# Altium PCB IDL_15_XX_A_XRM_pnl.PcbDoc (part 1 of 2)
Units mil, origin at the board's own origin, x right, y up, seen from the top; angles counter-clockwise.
Board outline 6130 x 3614.17 mil, 6 copper layers (Top Layer - SIG1, Layer 2 - GND1, Layer 3 - SIG2, Layer 4 - SIG3, Layer 5 - GND2, Bottom Layer - SIG4), stack 49.592 mil thick; 576 components, 385 nets, 1280 pads, 0 vias.
Unrouted connection lines stored in the file: 895.
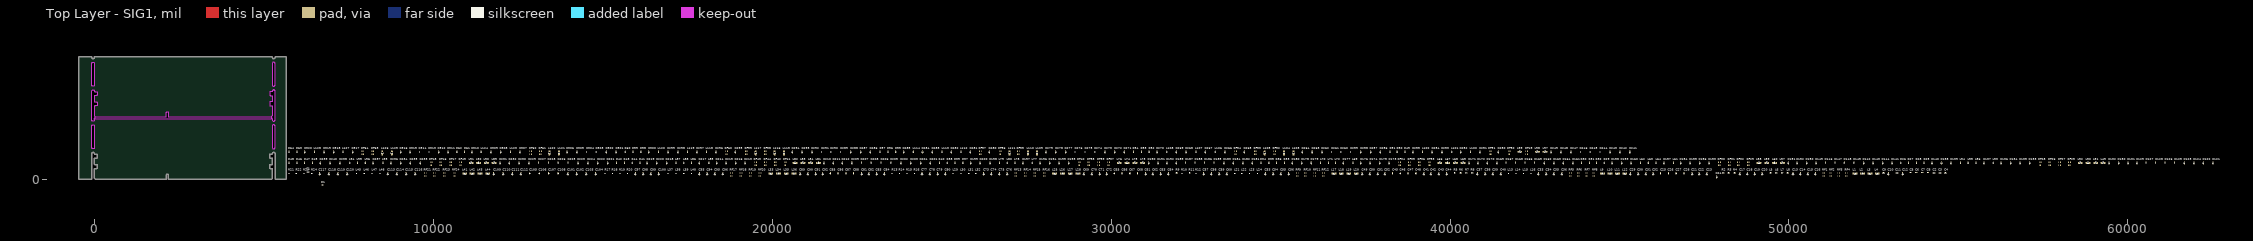
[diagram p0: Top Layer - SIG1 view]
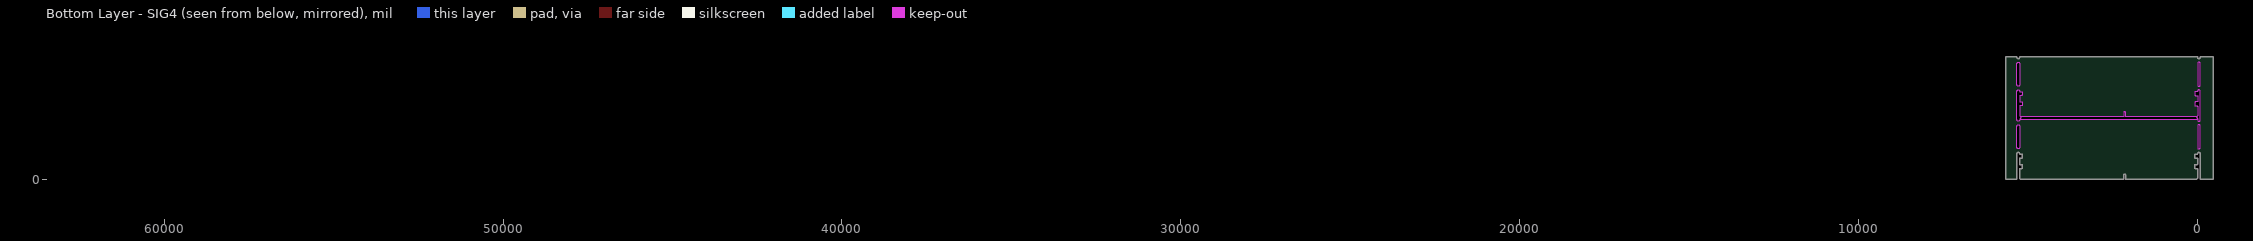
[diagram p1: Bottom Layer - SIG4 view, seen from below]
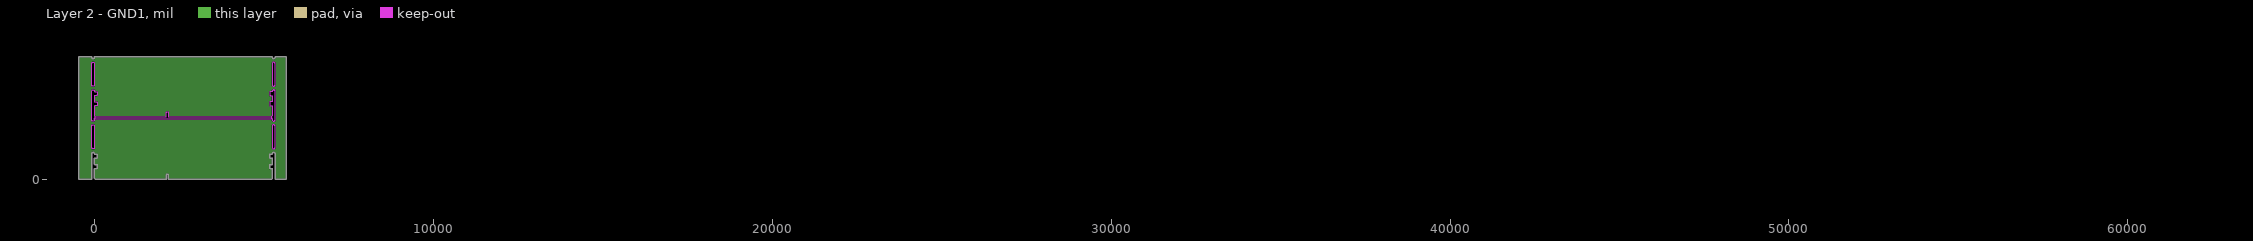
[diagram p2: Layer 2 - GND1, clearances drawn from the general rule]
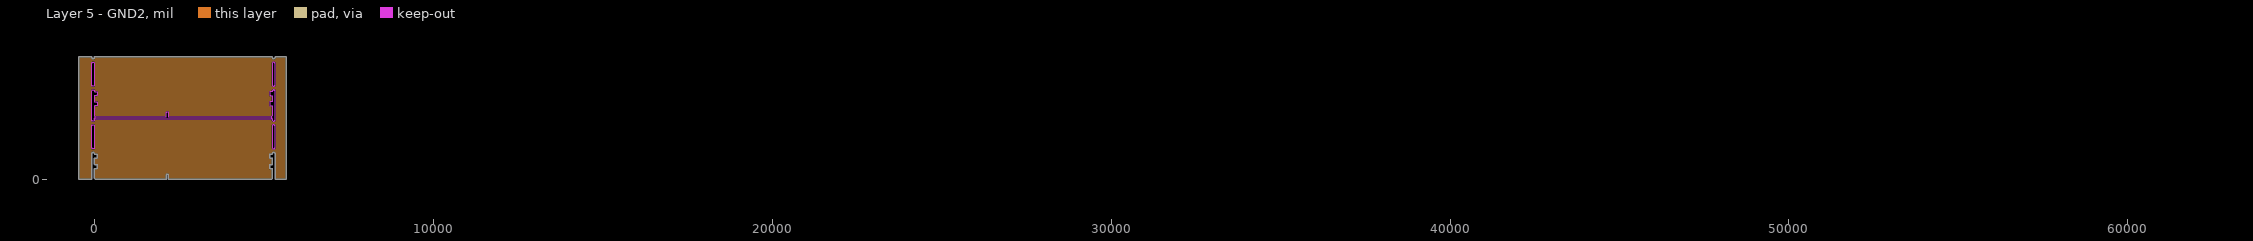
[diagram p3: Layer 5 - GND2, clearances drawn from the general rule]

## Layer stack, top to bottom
Top Solder: solder mask 0.4, Solder Resist, Dk 3.5
Top Layer - SIG1: signal copper 1.378
Dielectric 1: prepreg 8, FR-4, Dk 4.65
Layer 2 - GND1: plane copper 0.709
Dielectric 3: core 10, FR-4, Dk 4.65
Layer 3 - SIG2: signal copper 0.709
Dielectric 6: prepreg 8, FR-4, Dk 4.65
Layer 4 - SIG3: signal copper 0.709
Dielectric 5: core 10, FR-4, Dk 4.65
Layer 5 - GND2: plane copper 0.709
Dielectric 4: prepreg 8, FR-4, Dk 4.65
Bottom Layer - SIG4: signal copper 1.378
Bottom Solder: solder mask 0.4, Solder Resist, Dk 3.5

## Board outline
-465,0 -78.74,0 -78.74,751.97 cw(c-39.37,751.97) -39.37,791.34 cw(c-39.37,751.97) 0,751.97 ccw(c11.81,751.97) 11.81,740.16 62.99,740.16 cw(c62.99,720.47) 82.68,720.47 82.68,641.73 cw(c62.99,641.73) 62.99,622.05 11.81,622.05 ccw(c11.81,610.24) 0,610.24 0,444.88 ccw(c11.81,444.88) 11.81,433.07 62.99,433.07 cw(c62.99,413.39) 82.68,413.39 82.68,334.65 cw(c62.99,334.65) 62.99,314.96 11.81,314.96 ccw(c11.81,303.15) 0,303.15 0,29.53 29.53,0 2115.16,0 ccw(c2115.16,7.87) 2123.03,7.87 2123.03,120.08 cw(c2152.56,120.08) 2152.56,149.61 cw(c2152.56,120.08) 2182.09,120.08 2182.09,7.87 ccw(c2189.96,7.87) 2189.96,0 5220.47,0 5250,29.53 5250,303.15 ccw(c5238.19,303.15) 5238.19,314.96 5187.01,314.96 cw(c5187.01,334.65) 5167.32,334.65 5167.32,413.39 cw(c5187.01,413.39) 5187.01,433.07 5238.19,433.07 ccw(c5238.19,444.88) 5250,444.88 5250,610.24 ccw(c5238.19,610.24) 5238.19,622.05 5187.01,622.05 cw(c5187.01,641.73) 5167.32,641.73 5167.32,720.47 cw(c5187.01,720.47) 5187.01,740.16 5238.19,740.16 ccw(c5238.19,751.97) 5250,751.97 cw(c5289.37,751.97) 5289.37,791.34 cw(c5289.37,751.97) 5328.74,751.97 5328.74,0 5665,0 5665,3614 5328.74,3614 5328.74,3594.49 cw(c5289.37,3594.49) 5289.37,3555.12 cw(c5289.37,3594.49) 5250,3594.49 5250,3614.17 0,3614.17 0,3594.49 cw(c-39.37,3594.49) -39.37,3555.12 cw(c-39.37,3594.49) -78.74,3594.49 -78.74,3614 -465,3614
cut-out: -78.74,3413.39 cw(c-39.37,3413.39) -39.37,3452.76 cw(c-39.37,3413.39) 0,3413.39 0,2779.53 cw(c-39.37,2779.53) -39.37,2740.16 cw(c-39.37,2779.53) -78.74,2779.53
cut-out: -78.74,2598.43 cw(c-39.37,2598.43) -39.37,2637.8 cw(c-39.37,2598.43) 0,2598.43 ccw(c11.81,2598.43) 11.81,2586.61 62.99,2586.61 cw(c62.99,2566.93) 82.68,2566.93 82.68,2488.19 cw(c62.99,2488.19) 62.99,2468.5 11.81,2468.5 ccw(c11.81,2456.69) 0,2456.69 0,2291.34 ccw(c11.81,2291.34) 11.81,2279.53 62.99,2279.53 cw(c62.99,2259.84) 82.68,2259.84 82.68,2181.1 cw(c62.99,2181.1) 62.99,2161.42 11.81,2161.42 ccw(c11.81,2149.61) 0,2149.61 0,1875.98 29.53,1846.46 0,1767.72 0,1748.03 cw(c-39.37,1748.03) -39.37,1708.66 cw(c-39.37,1748.03) -78.74,1748.03
cut-out: 0,1767.72 29.53,1846.46 2115.16,1846.46 ccw(c2115.16,1854.33) 2123.03,1854.33 2123.03,1966.54 cw(c2152.56,1966.54) 2152.56,1996.06 cw(c2152.56,1966.54) 2182.09,1966.54 2182.09,1854.33 ccw(c2189.96,1854.33) 2189.96,1846.46 5220.47,1846.46 5250,1767.72
cut-out: 5328.74,2598.43 ccw(c5289.37,2598.43) 5289.37,2637.8 ccw(c5289.37,2598.43) 5250,2598.43 cw(c5238.19,2598.42) 5238.19,2586.61 5187.01,2586.61 ccw(c5187.01,2566.93) 5167.32,2566.93 5167.32,2488.19 ccw(c5187.01,2488.19) 5187.01,2468.5 5238.19,2468.5 cw(c5238.19,2456.69) 5250,2456.69 5250,2291.34 cw(c5238.19,2291.34) 5238.19,2279.53 5187.01,2279.53 ccw(c5187.01,2259.84) 5167.32,2259.84 5167.32,2181.1 ccw(c5187.01,2181.1) 5187.01,2161.42 5238.19,2161.42 cw(c5238.19,2149.61) 5250,2149.61 5250,1875.98 5220.47,1846.46 5212,1799 5250,1767.72 5250,1747.94 ccw(c5289.37,1748.03) 5328.74,1748.03
cut-out: 5328.74,1566.93 ccw(c5289.37,1566.93) 5289.37,1606.3 ccw(c5289.37,1566.93) 5250,1566.93 5250,933.07 ccw(c5289.37,933.07) 5289.37,893.7 ccw(c5289.37,933.07) 5328.74,933.07
cut-out: 5328.74,3413.39 ccw(c5289.37,3413.39) 5289.37,3452.76 ccw(c5289.37,3413.39) 5250,3413.39 5250,2779.53 ccw(c5289.37,2779.53) 5289.37,2740.16 ccw(c5289.37,2779.53) 5328.74,2779.53
cut-out: -78.74,1566.93 cw(c-39.37,1566.93) -39.37,1606.3 cw(c-39.37,1566.93) 0,1566.93 0,933.07 cw(c-39.37,933.07) -39.37,893.7 cw(c-39.37,933.07) -78.74,933.07

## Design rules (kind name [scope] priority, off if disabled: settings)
Clearance Clearance_KeepOut [Iskeepout] p1: gap=20
Clearance [All] p2: gap=7
HoleSize [All] p1: absolutevalues=TRUE maxlimit=129.92 minlimit=11.81 maxpercent=80.000 minpercent=20.000
MinimumSolderMaskSliver [All] p1: minsoldermaskwidth=5
PlaneClearance [All] p1: clearance=10
PlaneConnect PlaneConnect_vIA [ISvIA] p1: planeconnectstyle=Direct reliefexpansion=20 reliefentries=4 reliefconductorwidth=10 reliefairgap=10
PlaneConnect [All] p2: planeconnectstyle=Relief reliefexpansion=12 reliefentries=4 reliefconductorwidth=10 reliefairgap=8
PolygonConnect PolygonConnect_Via [IsVia or HasFootprint('ChipFET1206-8') or HasFootprint('MAXB2MPCBV') or HasFootprint('MAXB5MPCBV') or HasFootprint('MAXB6MPCBV')] p1: connectstyle=Direct reliefconductorwidth=10 reliefentries=4 polygonreliefangle="90 Angle" airgapwidth=10
PolygonConnect PolygonConnect_Main [All] p2: connectstyle=Relief reliefconductorwidth=10 reliefentries=4 polygonreliefangle="90 Angle" airgapwidth=10
RoomDefinition IDL_15_XX_A_XRM(6) [InComponentClass('IDL_15_XX_A_XRM(6)')] p1: confinementstyle=ConfineIn formatcopy=TRUE lockcomponents=FALSE outline 5709.39,685.64 45498.74,685.64 45498.74,963.21 5709.39,963.21
RoomDefinition IDL_15_XX_A_XRM(5) [InComponentClass('IDL_15_XX_A_XRM(5)')] p2: confinementstyle=ConfineIn formatcopy=TRUE lockcomponents=FALSE outline 5709.39,370.66 62693.47,370.66 62693.47,636.42 5709.39,636.42
RoomDefinition IDL_15_XX_A_XRM(4) [InComponentClass('IDL_15_XX_A_XRM(4)')] p3: confinementstyle=ConfineIn formatcopy=TRUE lockcomponents=FALSE outline 5709.39,55.68 5982.04,55.68 5982.04,225.97 5709.39,225.97
RoutingVias [All] p1: holewidth=11.81 width=25.59 viastyle="Through Hole" minholewidth=11.81 minwidth=25.59 maxholewidth=39.37 maxwidth=59.06
SilkToSilkClearance [All] p1: silktosilkclearance=5
SilkToSolderMaskClearance SilkscreenOverComponentPads [IsPad] p1: minsilkscreentomaskgap=5 clearancetoexposedcopper=TRUE
SolderMaskExpansion [All] p1: expansion=2
Width Width_Logo [HasFootprint('ITECH_LOGO')] p1: maxlimit=10 minlimit=1 preferedwidth=2
Width [All] p2: maxlimit=150 minlimit=6 preferedwidth=10 toplayer_prefwidth=8 midlayer1_prefwidth=8 midlayer2_minwidth=10 midlayer2_maxwidth=10 bottomlayer_prefwidth=8 minimp=50.000000 maximp=50.000000 favimp=50.000000
24 further rules are at their usual default settings.

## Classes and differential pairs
component class IDL_15_XX_A_XRM(3): K1
component class IDL_15_XX_A_XRM(4): C1 C2 C3 C4 C5 C6 C7 C8 C9 C10 C11 C12 C13 C14 C15 C16 C17 C18 C19 C20 C21 C22 C23 C24 C25 C26 C27 C28 C29 C30 C31 C32 C33 C34 C35 C36 C37 C38 C39 C40 C41 C42 C43 C44 C45 C46 C47 C48 C49 C50 C51 C52 C53 C54 C55 C56 C57 C58 C59 C60 C61 C62 C63 C64 C65 C66 C67 C68 C69 C70 C71 C72 C73 C74 C75 C76 C77 C78 C79 C80 C81 C82 C83 C84 C85 C86 C87 C88 C89 C90 C91 C92 C93 C94 C95 C96 C97 C98 C99 C100 C101 C102 C103 C104 C105 C106 C107 C108 C109 C110 C111 C112 C113 C114 C115 C116 C117 C118 C119 C120 L1 L2 L3 L4 L5 L6 L7 L8 L9 L10 L11 L12 L13 L14 L15 L16 L17 L18 L19 L20 L21 L22 L23 L24 L25 L26 L27 L28 L29 L30 L31 L32 L33 L34 L35 L36 L37 L38 L39 L40 L41 L42 L43 L44 L45 L46 L47 L48 R1 R2 R3 R4 R5 R6 R7 R8 R9 R10 R11 R12 R13 R14 R15 R16 R17 R18 R19 R20 R21 R22 R23 R24 RF1 RF2 RF3 RF4 RF5 RF6 RF7 RF8 RF9 RF10 RF11 RF12 RF13 RF14 RF15 RF16 RF17 RF18 RF19 RF20 RF21 RF22 RF23 RF24
component class IDL_15_XX_A_XRM(5): C121 C122 C123 C124 C125 C126 C127 C128 C129 C130 C131 C132 C133 C134 C135 C136 C137 C138 C139 C140 C141 C142 C143 C144 C145 C146 C147 C148 C149 C150 C151 C152 C153 C154 C155 C156 C157 C158 C159 C160 C161 C162 C163 C164 C165 C166 C167 C168 C169 C170 C171 C172 C173 C174 C175 C176 C177 C178 C179 C180 C181 C182 C183 C184 C185 C186 C187 C188 C189 C190 C191 C192 C193 C194 C195 C196 C197 C198 C199 C200 C201 C202 C203 C204 C205 C206 C207 C208 C209 C210 C211 C212 C213 C214 C215 C216 C217 C218 C219 C220 C221 C222 C223 C224 C225 C226 C227 C228 C229 C230 C231 C232 C233 C234 C235 C236 C237 C238 C239 C240 L49 L50 L51 L52 L53 L54 L55 L56 L57 L58 L59 L60 L61 L62 L63 L64 L65 L66 L67 L68 L69 L70 L71 L72 L73 L74 L75 L76 L77 L78 L79 L80 L81 L82 L83 L84 L85 L86 L87 L88 L89 L90 L91 L92 L93 L94 L95 L96 R25 R26 R27 R28 R29 R30 R31 R32 R33 R34 R35 R36 R37 R38 R39 R40 R41 R42 R43 R44 R45 R46 R47 R48 RF25 RF26 RF27 RF28 RF29 RF30 RF31 RF32 RF33 RF34 RF35 RF36 RF37 RF38 RF39 RF40 RF41 RF42 RF43 RF44 RF45 RF46 RF47 RF48
component class IDL_15_XX_A_XRM(6): C241 C242 C243 C244 C245 C246 C247 C248 C249 C250 C251 C252 C253 C254 C255 C256 C257 C258 C259 C260 C261 C262 C263 C264 C265 C266 C267 C268 C269 C270 C271 C272 C273 C274 C275 C276 C277 C278 C279 C280 C281 C282 C283 C284 C285 C286 C287 C288 C289 C290 C291 C292 C293 C294 C295 C296 C297 C298 C299 C300 C301 C302 C303 C304 C305 C306 C307 C308 C309 C310 C311 C312 C313 C314 C315 C316 C317 C318 C319 C320 L97 L98 L99 L100 L101 L102 L103 L104 L105 L106 L107 L108 L109 L110 L111 L112 L113 L114 L115 L116 L117 L118 L119 L120 L121 L122 L123 L124 L125 L126 L127 L128 R49 R50 R51 R52 R53 R54 R55 R56 R57 R58 R59 R60 R61 R62 R63 R64 RF49 RF50 RF51 RF52 RF53 RF54 RF55 RF56 RF57 RF58 RF59 RF60 RF61 RF62 RF63 RF64

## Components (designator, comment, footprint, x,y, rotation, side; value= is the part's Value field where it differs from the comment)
C1 "10nF" CC0603RF1R 6301.18,216.54 r0 top
C2 "10nF" CC0603RF1R 54284.6,185.61 r0 top
C3 "10nF" CC0603RF1R 54453.9,185.61 r0 top
C4 "10nF" CC0603RF1R 54624.18,185.61 r0 top
C5 "100nF" CC0402N1X 53589.68,192.5 r0 top
C6 "100nF" CC0402N1X 53759.97,192.5 r0 top
C7 "100nF" CC0402N1X 53930.25,192.5 r0 top
C8 "100nF" CC0402N1X 54100.53,192.5 r0 top
C9 "1uF" CC0603RF1R 52792.4,185.61 r0 top
C10 "1uF" CC0603RF1R 52937.09,160.02 r90 top
C11 "1uF" CC0603RF1R 53183.17,185.61 r0 top
C12 "1uF" CC0603RF1R 53356.4,160.02 r90 top
C13 "10nF" CC0603RF1R 50120.02,160.02 r90 top
C14 "10nF" CC0603RF1R 50340.51,160.02 r90 top
C15 "10nF" CC0603RF1R 50560.01,160.02 r90 top
C16 "10nF" CC0603RF1R 50780.49,160.02 r90 top
C17 "10nF" CC0603RF1R 48550.07,160.02 r90 top
C18 "10nF" CC0603RF1R 48770.55,160.02 r90 top
C19 "10nF" CC0603RF1R 48990.05,160.02 r90 top
C20 "10nF" CC0603RF1R 49210.53,160.02 r90 top
C21 "10nF" CC0603RF1R 47140.55,160.02 r90 top
C22 "10nF" CC0603RF1R 47350.2,160.02 r90 top
C23 "10nF" CC0603RF1R 47580.53,160.02 r90 top
C24 "10nF" CC0603RF1R 47867.13,66.93 r90 top
C25 "100nF" CC0402N1X 46213.34,173.8 r90 top
C26 "100nF" CC0402N1X 46443.66,173.8 r90 top
C27 "100nF" CC0402N1X 46673,173.8 r90 top
C28 "100nF" CC0402N1X 46903.33,173.8 r90 top
C29 "1uF" CC0603RF1R 45320.58,160.02 r90 top
C30 "1uF" CC0603RF1R 45550.9,160.02 r90 top
C31 "1uF" CC0603RF1R 45780.24,160.02 r90 top
C32 "1uF" CC0603RF1R 45990.89,160.02 r90 top
C33 "10nF" CC0603RF1R 42607.85,160.02 r90 top
C34 "10nF" CC0603RF1R 42837.19,160.02 r90 top
C35 "10nF" CC0603RF1R 43067.51,160.02 r90 top
C36 "10nF" CC0603RF1R 43297.84,160.02 r90 top
C37 "10nF" CC0603RF1R 40807.56,160.02 r90 top
C38 "10nF" CC0603RF1R 41037.89,160.02 r90 top
C39 "10nF" CC0603RF1R 41267.23,160.02 r90 top
C40 "10nF" CC0603RF1R 41497.56,160.02 r90 top
C41 "10nF" CC0603RF1R 39227.76,160.02 r90 top
C42 "10nF" CC0603RF1R 39437.42,160.02 r90 top
C43 "10nF" CC0603RF1R 39667.74,160.02 r90 top
C44 "10nF" CC0603RF1R 39898.07,160.02 r90 top
C45 "100nF" CC0402N1X 38300.55,173.8 r90 top
C46 "100nF" CC0402N1X 38530.88,173.8 r90 top
C47 "100nF" CC0402N1X 38761.2,173.8 r90 top
C48 "100nF" CC0402N1X 38990.54,173.8 r90 top
C49 "1uF" CC0603RF1R 37407.79,160.02 r90 top
C50 "1uF" CC0603RF1R 37638.12,160.02 r90 top
C51 "1uF" CC0603RF1R 37867.46,160.02 r90 top
C52 "1uF" CC0603RF1R 38078.1,160.02 r90 top
C53 "10nF" CC0603RF1R 34548.4,160.02 r90 top
C54 "10nF" CC0603RF1R 34778.72,160.02 r90 top
C55 "10nF" CC0603RF1R 35008.07,160.02 r90 top
C56 "10nF" CC0603RF1R 35238.39,160.02 r90 top
C57 "10nF" CC0603RF1R 32728.43,160.02 r90 top
C58 "10nF" CC0603RF1R 32958.75,160.02 r90 top
C59 "10nF" CC0603RF1R 33188.1,160.02 r90 top
C60 "10nF" CC0603RF1R 33418.42,160.02 r90 top
C61 "10nF" CC0603RF1R 31018.7,160.02 r90 top
C62 "10nF" CC0603RF1R 31228.35,160.02 r90 top
C63 "10nF" CC0603RF1R 31458.68,160.02 r90 top
C64 "10nF" CC0603RF1R 31689.01,160.02 r90 top
C65 "100nF" CC0402N1X 30091.49,173.8 r90 top
C66 "100nF" CC0402N1X 30321.81,173.8 r90 top
C67 "100nF" CC0402N1X 30551.16,173.8 r90 top
C68 "100nF" CC0402N1X 30781.48,173.8 r90 top
C69 "1uF" CC0603RF1R 29198.73,160.02 r90 top
C70 "1uF" CC0603RF1R 29429.05,160.02 r90 top
C71 "1uF" CC0603RF1R 29658.4,160.02 r90 top
C72 "1uF" CC0603RF1R 29869.04,160.02 r90 top
C73 "10nF" CC0603RF1R 26238.94,160.02 r90 top
C74 "10nF" CC0603RF1R 26469.26,160.02 r90 top
C75 "10nF" CC0603RF1R 26699.59,160.02 r90 top
C76 "10nF" CC0603RF1R 26928.93,160.02 r90 top
C77 "10nF" CC0603RF1R 24418.97,160.02 r90 top
C78 "10nF" CC0603RF1R 24649.29,160.02 r90 top
C79 "10nF" CC0603RF1R 24879.62,160.02 r90 top
C80 "10nF" CC0603RF1R 25108.96,160.02 r90 top
C81 "10nF" CC0603RF1R 22639.35,160.02 r90 top
C82 "10nF" CC0603RF1R 22849.99,160.02 r90 top
C83 "10nF" CC0603RF1R 23079.33,160.02 r90 top
C84 "10nF" CC0603RF1R 23309.66,160.02 r90 top
C85 "100nF" CC0402N1X 21713.13,173.8 r90 top
C86 "100nF" CC0402N1X 21942.47,173.8 r90 top
C87 "100nF" CC0402N1X 22172.79,173.8 r90 top
C88 "100nF" CC0402N1X 22402.14,173.8 r90 top
C89 "1uF" CC0603RF1R 20819.38,160.02 r90 top
C90 "1uF" CC0603RF1R 21049.71,160.02 r90 top
C91 "1uF" CC0603RF1R 21280.03,160.02 r90 top
C92 "1uF" CC0603RF1R 21489.69,160.02 r90 top
C93 "10nF" CC0603RF1R 17849.75,160.02 r90 top
C94 "10nF" CC0603RF1R 18080.07,160.02 r90 top
C95 "10nF" CC0603RF1R 18310.4,160.02 r90 top
C96 "10nF" CC0603RF1R 18539.74,160.02 r90 top
C97 "10nF" CC0603RF1R 15959.89,160.02 r90 top
C98 "10nF" CC0603RF1R 16190.22,160.02 r90 top
C99 "10nF" CC0603RF1R 16420.54,160.02 r90 top
C100 "10nF" CC0603RF1R 16649.89,160.02 r90 top
C101 "10nF" CC0603RF1R 13970.62,160.02 r90 top
C102 "10nF" CC0603RF1R 14230.48,160.02 r90 top
C103 "10nF" CC0603RF1R 14511,160.02 r90 top
C104 "10nF" CC0603RF1R 14790.54,160.02 r90 top
C105 "100nF" CC0402N1X 12843.6,173.8 r90 top
C106 "100nF" CC0402N1X 13124.12,173.8 r90 top
C107 "100nF" CC0402N1X 13403.67,173.8 r90 top
C108 "100nF" CC0402N1X 13683.21,173.8 r90 top
C109 "1uF" CC0603RF1R 11780.55,160.02 r90 top
C110 "1uF" CC0603RF1R 12061.08,160.02 r90 top
C111 "1uF" CC0603RF1R 12330.78,160.02 r90 top
C112 "1uF" CC0603RF1R 12580.79,160.02 r90 top
C113 "10nF" CC0603RF1R 8654.42,160.02 r90 top
C114 "10nF" CC0603RF1R 8925.1,160.02 r90 top
C115 "10nF" CC0603RF1R 9194.8,160.02 r90 top
C116 "10nF" CC0603RF1R 9464.5,160.02 r90 top
C117 "10nF" CC0603RF1R 6644.48,160.02 r90 top
C118 "10nF" CC0603RF1R 6915.16,160.02 r90 top
C119 "10nF" CC0603RF1R 7184.86,160.02 r90 top
C120 "10nF" CC0603RF1R 7454.56,160.02 r90 top
C121 "10nF" CC0603RF1R 62507.44,475 r90 top
C122 "10nF" CC0603RF1R 62227.9,475 r90 top
C123 "10nF" CC0603RF1R 61667.83,475 r90 top
C124 "10nF" CC0603RF1R 61947.37,475 r90 top
C125 "100nF" CC0402N1X 61380.42,488.78 r90 top
C126 "100nF" CC0402N1X 61100.87,488.78 r90 top
C127 "100nF" CC0402N1X 60540.81,488.78 r90 top
C128 "100nF" CC0402N1X 60820.35,488.78 r90 top
C129 "1uF" CC0603RF1R 60268.16,475 r90 top
C130 "1uF" CC0603RF1R 59727.78,475 r90 top
C131 "1uF" CC0603RF1R 60007.32,475 r90 top
C132 "1uF" CC0603RF1R 59448.23,475 r90 top
C133 "10nF" CC0603RF1R 57101.66,475 r90 top
C134 "10nF" CC0603RF1R 56541.6,475 r90 top
C135 "10nF" CC0603RF1R 56821.14,475 r90 top
C136 "10nF" CC0603RF1R 56261.07,475 r90 top
C137 "10nF" CC0603RF1R 55751.2,475 r90 top
C138 "10nF" CC0603RF1R 54502.13,475 r90 top
C139 "10nF" CC0603RF1R 54781.67,475 r90 top
C140 "10nF" CC0603RF1R 54221.6,475 r90 top
C141 "10nF" CC0603RF1R 53042.41,475 r90 top
C142 "10nF" CC0603RF1R 52201.82,475 r90 top
C143 "10nF" CC0603RF1R 52482.34,475 r90 top
C144 "10nF" CC0603RF1R 52761.88,475 r90 top
C145 "100nF" CC0402N1X 51915.39,488.78 r90 top
C146 "100nF" CC0402N1X 51074.79,488.78 r90 top
C147 "100nF" CC0402N1X 51355.32,488.78 r90 top
C148 "100nF" CC0402N1X 51634.86,488.78 r90 top
C149 "1uF" CC0603RF1R 50802.14,475 r90 top
C150 "1uF" CC0603RF1R 50522.6,475 r90 top
C151 "1uF" CC0603RF1R 49982.22,475 r90 top
C152 "1uF" CC0603RF1R 50242.08,475 r90 top
C153 "10nF" CC0603RF1R 47642.54,475 r90 top
C154 "10nF" CC0603RF1R 46802.93,475 r90 top
C155 "10nF" CC0603RF1R 47082.47,475 r90 top
C156 "10nF" CC0603RF1R 47363,475 r90 top
C157 "10nF" CC0603RF1R 46312.75,475 r90 top
C158 "10nF" CC0603RF1R 44783.15,475 r90 top
C159 "10nF" CC0603RF1R 45062.69,475 r90 top
C160 "10nF" CC0603RF1R 45343.22,475 r90 top
C161 "10nF" CC0603RF1R 43623.64,475 r90 top
C162 "10nF" CC0603RF1R 42783.05,475 r90 top
C163 "10nF" CC0603RF1R 43063.58,475 r90 top
C164 "10nF" CC0603RF1R 43343.12,475 r90 top
C165 "100nF" CC0402N1X 42496.62,488.78 r90 top
C166 "100nF" CC0402N1X 42216.09,488.78 r90 top
C167 "100nF" CC0402N1X 41656.03,488.78 r90 top
C168 "100nF" CC0402N1X 41936.55,488.78 r90 top
C169 "1uF" CC0603RF1R 41383.38,475 r90 top
C170 "1uF" CC0603RF1R 41103.84,475 r90 top
C171 "1uF" CC0603RF1R 40563.45,475 r90 top
C172 "1uF" CC0603RF1R 40823.31,475 r90 top
C173 "10nF" CC0603RF1R 38204.09,475 r90 top
C174 "10nF" CC0603RF1R 37644.02,475 r90 top
C175 "10nF" CC0603RF1R 37924.55,475 r90 top
C176 "10nF" CC0603RF1R 37364.48,475 r90 top
C177 "10nF" CC0603RF1R 36854.61,475 r90 top
C178 "10nF" CC0603RF1R 35624.24,475 r90 top
C179 "10nF" CC0603RF1R 35904.76,475 r90 top
C180 "10nF" CC0603RF1R 35344.7,475 r90 top
C181 "10nF" CC0603RF1R 34164.52,475 r90 top
C182 "10nF" CC0603RF1R 33884.98,475 r90 top
C183 "10nF" CC0603RF1R 33324.91,475 r90 top
C184 "10nF" CC0603RF1R 33604.45,475 r90 top
C185 "100nF" CC0402N1X 33037.5,488.78 r90 top
C186 "100nF" CC0402N1X 32757.96,488.78 r90 top
C187 "100nF" CC0402N1X 32197.89,488.78 r90 top
C188 "100nF" CC0402N1X 32477.43,488.78 r90 top
C189 "1uF" CC0603RF1R 31925.24,475 r90 top
C190 "1uF" CC0603RF1R 31105.32,475 r90 top
C191 "1uF" CC0603RF1R 31384.86,475 r90 top
C192 "1uF" CC0603RF1R 31644.71,475 r90 top
C193 "10nF" CC0603RF1R 28744.96,475 r90 top
C194 "10nF" CC0603RF1R 28185.88,475 r90 top
C195 "10nF" CC0603RF1R 28465.42,475 r90 top
C196 "10nF" CC0603RF1R 27905.36,475 r90 top
C197 "10nF" CC0603RF1R 27395.49,475 r90 top
C198 "10nF" CC0603RF1R 26425.95,475 r90 top
C199 "10nF" CC0603RF1R 25856.04,475 r90 top
C200 "10nF" CC0603RF1R 26135.59,475 r90 top
C201 "10nF" CC0603RF1R 24666.03,475 r90 top
C202 "10nF" CC0603RF1R 23795.9,475 r90 top
C203 "10nF" CC0603RF1R 24086.27,475 r90 top
C204 "10nF" CC0603RF1R 24375.66,475 r90 top
C205 "100nF" CC0402N1X 23498.65,488.78 r90 top
C206 "100nF" CC0402N1X 23209.26,488.78 r90 top
C207 "100nF" CC0402N1X 22629.51,488.78 r90 top
C208 "100nF" CC0402N1X 22918.89,488.78 r90 top
C209 "1uF" CC0603RF1R 22346.03,475 r90 top
C210 "1uF" CC0603RF1R 21526.11,475 r90 top
C211 "1uF" CC0603RF1R 21806.63,475 r90 top
C212 "1uF" CC0603RF1R 22066.49,475 r90 top
C213 "10nF" CC0603RF1R 19200.21,475 r90 top
C214 "10nF" CC0603RF1R 18359.62,475 r90 top
C215 "10nF" CC0603RF1R 18640.14,475 r90 top
C216 "10nF" CC0603RF1R 18919.68,475 r90 top
C217 "10nF" CC0603RF1R 17849.75,475 r90 top
C218 "10nF" CC0603RF1R 16880.21,475 r90 top
C219 "10nF" CC0603RF1R 16310.3,475 r90 top
C220 "10nF" CC0603RF1R 16589.84,475 r90 top
C221 "10nF" CC0603RF1R 15139.97,475 r90 top
C222 "10nF" CC0603RF1R 14850.59,475 r90 top
C223 "10nF" CC0603RF1R 14270.83,475 r90 top
C224 "10nF" CC0603RF1R 14560.22,475 r90 top
C225 "100nF" CC0402N1X 13973.57,488.78 r90 top
C226 "100nF" CC0402N1X 13683.21,488.78 r90 top
C227 "100nF" CC0402N1X 13103.45,488.78 r90 top
C228 "100nF" CC0402N1X 13393.82,488.78 r90 top
C229 "1uF" CC0603RF1R 12820.96,475 r90 top
C230 "1uF" CC0603RF1R 12530.59,475 r90 top
C231 "1uF" CC0603RF1R 11970.52,475 r90 top
C232 "1uF" CC0603RF1R 12241.21,475 r90 top
C233 "10nF" CC0603RF1R 9614.11,475 r90 top
C234 "10nF" CC0603RF1R 9034.36,475 r90 top
C235 "10nF" CC0603RF1R 9324.73,475 r90 top
C236 "10nF" CC0603RF1R 8744.97,475 r90 top
C237 "10nF" CC0603RF1R 8224.28,475 r90 top
C238 "10nF" CC0603RF1R 7244.9,475 r90 top
C239 "10nF" CC0603RF1R 6665.15,475 r90 top
C240 "10nF" CC0603RF1R 6954.53,475 r90 top
C241 "10nF" CC0603RF1R 45302.86,801.78 r90 top
C242 "10nF" CC0603RF1R 45012.49,801.78 r90 top
C243 "10nF" CC0603RF1R 44723.11,801.78 r90 top
C244 "100nF" CC0402N1X 44425.85,816.55 r90 top
C245 "100nF" CC0402N1X 44135.48,816.55 r90 top
C246 "100nF" CC0402N1X 43846.1,816.55 r90 top
C247 "1uF" CC0603RF1R 43562.62,801.78 r90 top
C248 "1uF" CC0603RF1R 43273.23,801.78 r90 top
C249 "1uF" CC0603RF1R 42982.86,801.78 r90 top
C250 "10nF" CC0603RF1R 41423.73,801.78 r90 top
C251 "10nF" CC0603RF1R 40883.35,801.78 r90 top
C252 "10nF" CC0603RF1R 40313.44,801.78 r90 top
C253 "10nF" CC0603RF1R 39763.22,801.78 r90 top
C254 "10nF" CC0603RF1R 39473.83,801.78 r90 top
C255 "10nF" CC0603RF1R 38903.93,801.78 r90 top
C256 "10nF" CC0603RF1R 37944.23,801.78 r90 top
C257 "10nF" CC0603RF1R 37653.86,801.78 r90 top
C258 "10nF" CC0603RF1R 37363.5,801.78 r90 top
C259 "100nF" CC0402N1X 37067.22,816.55 r90 top
C260 "100nF" CC0402N1X 36776.85,816.55 r90 top
C261 "100nF" CC0402N1X 36507.15,816.55 r90 top
C262 "1uF" CC0603RF1R 36223.68,801.78 r90 top
C263 "1uF" CC0603RF1R 35934.29,801.78 r90 top
C264 "1uF" CC0603RF1R 35643.92,801.78 r90 top
C265 "10nF" CC0603RF1R 33933.21,801.78 r90 top
C266 "10nF" CC0603RF1R 33353.46,801.78 r90 top
C267 "10nF" CC0603RF1R 32783.55,801.78 r90 top
C268 "10nF" CC0603RF1R 32213.64,801.78 r90 top
C269 "10nF" CC0603RF1R 31924.25,801.78 r90 top
C270 "10nF" CC0603RF1R 31354.34,801.78 r90 top
C271 "10nF" CC0603RF1R 30393.67,801.78 r90 top
C272 "10nF" CC0603RF1R 30104.28,801.78 r90 top
C273 "10nF" CC0603RF1R 29813.91,801.78 r90 top
C274 "100nF" CC0402N1X 29517.64,816.55 r90 top
C275 "100nF" CC0402N1X 29227.27,816.55 r90 top
C276 "100nF" CC0402N1X 28936.9,816.55 r90 top
C277 "1uF" CC0603RF1R 28654.41,801.78 r90 top
C278 "1uF" CC0603RF1R 28364.04,801.78 r90 top
C279 "1uF" CC0603RF1R 28074.66,801.78 r90 top
C280 "10nF" CC0603RF1R 26404.3,801.78 r90 top
C281 "10nF" CC0603RF1R 25844.23,801.78 r90 top
C282 "10nF" CC0603RF1R 25284.17,801.78 r90 top
C283 "10nF" CC0603RF1R 24724.1,801.78 r90 top
C284 "10nF" CC0603RF1R 24433.73,801.78 r90 top
C285 "10nF" CC0603RF1R 23874.65,801.78 r90 top
C286 "10nF" CC0603RF1R 22894.29,801.78 r90 top
C287 "10nF" CC0603RF1R 22604.9,801.78 r90 top
C288 "10nF" CC0603RF1R 22314.53,801.78 r90 top
C289 "100nF" CC0402N1X 22017.27,816.55 r90 top
C290 "100nF" CC0402N1X 21727.89,816.55 r90 top
C291 "100nF" CC0402N1X 21457.21,816.55 r90 top
C292 "1uF" CC0603RF1R 21174.71,801.78 r90 top
C293 "1uF" CC0603RF1R 20884.35,801.78 r90 top
C294 "1uF" CC0603RF1R 20594.96,801.78 r90 top
C295 "10nF" CC0603RF1R 18913.78,801.78 r90 top
C296 "10nF" CC0603RF1R 18334.02,801.78 r90 top
C297 "10nF" CC0603RF1R 17773.96,801.78 r90 top
C298 "10nF" CC0603RF1R 17214.87,801.78 r90 top
C299 "10nF" CC0603RF1R 16924.51,801.78 r90 top
C300 "10nF" CC0603RF1R 16354.6,801.78 r90 top
C301 "10nF" CC0603RF1R 15394.9,801.78 r90 top
C302 "10nF" CC0603RF1R 15104.54,801.78 r90 top
C303 "100nF" CC0402N1X 14807.28,816.55 r90 top
C304 "100nF" CC0402N1X 14517.89,816.55 r90 top
C305 "1uF" CC0603RF1R 14234.41,801.78 r90 top
C306 "1uF" CC0603RF1R 13945.03,801.78 r90 top
C307 "10nF" CC0603RF1R 12554.21,801.78 r90 top
C308 "10nF" CC0603RF1R 11984.3,801.78 r90 top
C309 "10nF" CC0603RF1R 11694.92,801.78 r90 top
C310 "10nF" CC0603RF1R 11134.85,801.78 r90 top
C311 "10nF" CC0603RF1R 10435.02,801.78 r90 top
C312 "10nF" CC0603RF1R 10154.49,801.78 r90 top
C313 "100nF" CC0402N1X 9868.06,816.55 r90 top
C314 "100nF" CC0402N1X 9587.53,816.55 r90 top
C315 "1uF" CC0603RF1R 9314.88,801.78 r90 top
C316 "1uF" CC0603RF1R 9035.34,801.78 r90 top
C317 "10nF" CC0603RF1R 7615,801.78 r90 top
C318 "10nF" CC0603RF1R 7054.93,801.78 r90 top
C319 "10nF" CC0603RF1R 6774.4,801.78 r90 top
C320 "10nF" CC0603RF1R 6204.49,801.78 r90 top
L1 "1.5uH" LC1008N1R 51953.77,167.89 r0 top
L2 "1.5uH" LC1008N1R 52170.32,167.89 r0 top
L3 "1.5uH" LC1008N1R 52387.85,167.89 r0 top
L4 "1.5uH" LC1008N1R 52604.4,167.89 r0 top
L5 "0.5nH" LC0402N1R 49458.57,187.58 r0 top
L6 "0.5nH" LC0402N1R 49627.87,187.58 r0 top
L7 "0.5nH" LC0402N1R 49798.16,187.58 r0 top
L8 "0.5nH" LC0402N1R 49968.44,187.58 r0 top
L9 "1.5uH" LC1008N1R 44501.64,167.89 r0 top
L10 "1.5uH" LC1008N1R 44718.19,167.89 r0 top
L11 "1.5uH" LC1008N1R 44937.68,167.89 r0 top
L12 "1.5uH" LC1008N1R 45154.23,167.89 r0 top
L13 "0.5nH" LC0402N1R 41725.91,167.89 r90 top
L14 "0.5nH" LC0402N1R 41945.41,167.89 r90 top
L15 "0.5nH" LC0402N1R 42165.9,167.89 r90 top
L16 "0.5nH" LC0402N1R 42385.39,167.89 r90 top
L17 "1.5uH" LC1008N1R 36572.12,167.89 r0 top
L18 "1.5uH" LC1008N1R 36791.62,167.89 r0 top
L19 "1.5uH" LC1008N1R 37012.1,167.89 r0 top
L20 "1.5uH" LC1008N1R 37231.6,167.89 r0 top
L21 "0.5nH" LC0402N1R 33646.78,167.89 r90 top
L22 "0.5nH" LC0402N1R 33856.43,167.89 r90 top
L23 "0.5nH" LC0402N1R 34086.76,167.89 r90 top
L24 "0.5nH" LC0402N1R 34316.1,167.89 r90 top
L25 "1.5uH" LC1008N1R 28332.54,167.89 r0 top
L26 "1.5uH" LC1008N1R 28562.87,167.89 r0 top
L27 "1.5uH" LC1008N1R 28793.2,167.89 r0 top
L28 "1.5uH" LC1008N1R 29022.54,167.89 r0 top
L29 "0.5nH" LC0402N1R 25337.32,167.89 r90 top
L30 "0.5nH" LC0402N1R 25567.64,167.89 r90 top
L31 "0.5nH" LC0402N1R 25796.99,167.89 r90 top
L32 "0.5nH" LC0402N1R 26007.63,167.89 r90 top
L33 "1.5uH" LC1008N1R 19954.18,167.89 r0 top
L34 "1.5uH" LC1008N1R 20183.52,167.89 r0 top
L35 "1.5uH" LC1008N1R 20413.85,167.89 r0 top
L36 "1.5uH" LC1008N1R 20644.18,167.89 r0 top
L37 "0.5nH" LC0402N1R 16928.44,167.89 r90 top
L38 "0.5nH" LC0402N1R 17157.79,167.89 r90 top
L39 "0.5nH" LC0402N1R 17388.11,167.89 r90 top
L40 "0.5nH" LC0402N1R 17618.44,167.89 r90 top
L41 "1.5uH" LC1008N1R 10928.15,167.89 r0 top
L42 "1.5uH" LC1008N1R 11144.7,167.89 r0 top
L43 "1.5uH" LC1008N1R 11375.02,167.89 r0 top
L44 "1.5uH" LC1008N1R 11605.35,167.89 r0 top
L45 "0.5nH" LC0402N1R 7733.11,167.89 r90 top
L46 "0.5nH" LC0402N1R 7962.45,167.89 r90 top
L47 "0.5nH" LC0402N1R 8192.78,167.89 r90 top
L48 "0.5nH" LC0402N1R 8422.12,167.89 r90 top
L49 "1.5uH" LC1008N1R 59272.05,482.87 r0 top
L50 "1.5uH" LC1008N1R 58825.17,482.87 r0 top
L51 "1.5uH" LC1008N1R 59055.5,482.87 r0 top
L52 "1.5uH" LC1008N1R 58594.85,482.87 r0 top
L53 "0.5nH" LC0402N1R 56029.76,482.87 r90 top
L54 "0.5nH" LC0402N1R 55059.24,482.87 r90 top
L55 "0.5nH" LC0402N1R 55289.57,482.87 r90 top
L56 "0.5nH" LC0402N1R 55519.89,482.87 r90 top
L57 "1.5uH" LC1008N1R 49806.03,482.87 r0 top
L58 "1.5uH" LC1008N1R 49116.04,482.87 r0 top
L59 "1.5uH" LC1008N1R 49346.36,482.87 r0 top
L60 "1.5uH" LC1008N1R 49576.69,482.87 r0 top
L61 "0.5nH" LC0402N1R 46591.31,482.87 r90 top
L62 "0.5nH" LC0402N1R 45620.79,482.87 r90 top
L63 "0.5nH" LC0402N1R 45851.11,482.87 r90 top
L64 "0.5nH" LC0402N1R 46080.46,482.87 r90 top
L65 "1.5uH" LC1008N1R 40387.27,482.87 r0 top
L66 "1.5uH" LC1008N1R 39697.27,482.87 r0 top
L67 "1.5uH" LC1008N1R 39927.6,482.87 r0 top
L68 "1.5uH" LC1008N1R 40157.92,482.87 r0 top
L69 "0.5nH" LC0402N1R 37132.19,482.87 r90 top
L70 "0.5nH" LC0402N1R 36182.34,482.87 r90 top
L71 "0.5nH" LC0402N1R 36412.66,482.87 r90 top
L72 "0.5nH" LC0402N1R 36622.32,482.87 r90 top
L73 "1.5uH" LC1008N1R 30929.13,482.87 r0 top
L74 "1.5uH" LC1008N1R 30469.46,482.87 r0 top
L75 "1.5uH" LC1008N1R 30698.8,482.87 r0 top
L76 "1.5uH" LC1008N1R 30239.13,482.87 r0 top
L77 "0.5nH" LC0402N1R 27673.06,482.87 r90 top
L78 "0.5nH" LC0402N1R 27163.19,482.87 r90 top
L79 "0.5nH" LC0402N1R 26703.53,482.87 r90 top
L80 "0.5nH" LC0402N1R 26933.85,482.87 r90 top
L81 "1.5uH" LC1008N1R 21363.7,482.87 r0 top
L82 "1.5uH" LC1008N1R 20673.7,482.87 r0 top
L83 "1.5uH" LC1008N1R 20904.03,482.87 r0 top
L84 "1.5uH" LC1008N1R 21133.37,482.87 r0 top
L85 "0.5nH" LC0402N1R 18128.31,482.87 r90 top
L86 "0.5nH" LC0402N1R 17618.44,482.87 r90 top
L87 "0.5nH" LC0402N1R 17157.79,482.87 r90 top
L88 "0.5nH" LC0402N1R 17388.11,482.87 r90 top
L89 "1.5uH" LC1008N1R 11794.33,482.87 r0 top
L90 "1.5uH" LC1008N1R 11564.99,482.87 r0 top
L91 "1.5uH" LC1008N1R 11118.12,482.87 r0 top
L92 "1.5uH" LC1008N1R 11334.67,482.87 r0 top
L93 "0.5nH" LC0402N1R 8512.68,482.87 r90 top
L94 "0.5nH" LC0402N1R 7532.32,482.87 r90 top
L95 "0.5nH" LC0402N1R 7762.64,482.87 r90 top
L96 "0.5nH" LC0402N1R 7992.97,482.87 r90 top
L97 "1.5uH" LC1008N1R 42806.67,809.66 r0 top
L98 "1.5uH" LC1008N1R 42577.33,809.66 r0 top
L99 "1.5uH" LC1008N1R 42057.62,809.66 r0 top
L100 "0.5nH" LC0402N1R 40601.84,809.66 r90 top
L101 "0.5nH" LC0402N1R 40051.62,809.66 r90 top
L102 "0.5nH" LC0402N1R 39191.34,809.66 r90 top
L103 "1.5uH" LC1008N1R 35382.1,774.22 r90 top
L104 "1.5uH" LC1008N1R 35101.57,774.22 r90 top
L105 "1.5uH" LC1008N1R 34531.66,774.22 r90 top
L106 "0.5nH" LC0402N1R 33071.95,809.66 r90 top
L107 "0.5nH" LC0402N1R 32502.04,809.66 r90 top
L108 "0.5nH" LC0402N1R 31641.76,809.66 r90 top
L109 "1.5uH" LC1008N1R 27812.83,774.22 r90 top
L110 "1.5uH" LC1008N1R 27542.15,774.22 r90 top
L111 "1.5uH" LC1008N1R 27001.77,774.22 r90 top
L112 "0.5nH" LC0402N1R 25571.58,809.66 r90 top
L113 "0.5nH" LC0402N1R 25012.5,809.66 r90 top
L114 "0.5nH" LC0402N1R 24162.06,809.66 r90 top
L115 "1.5uH" LC1008N1R 20342.98,774.22 r90 top
L116 "1.5uH" LC1008N1R 20072.3,774.22 r90 top
L117 "1.5uH" LC1008N1R 19512.23,774.22 r90 top
L118 "0.5nH" LC0402N1R 18062.36,809.66 r90 top
L119 "0.5nH" LC0402N1R 17502.29,809.66 r90 top
L120 "0.5nH" LC0402N1R 16642.01,809.66 r90 top
L121 "1.5uH" LC1008N1R 13702.89,774.22 r90 top
L122 "1.5uH" LC1008N1R 13422.37,774.22 r90 top
L123 "0.5nH" LC0402N1R 12272.7,809.66 r90 top
L124 "0.5nH" LC0402N1R 11412.43,809.66 r90 top
L125 "1.5uH" LC1008N1R 8773.52,774.22 r90 top
L126 "1.5uH" LC1008N1R 8492.99,774.22 r90 top
L127 "0.5nH" LC0402N1R 7332.5,809.66 r90 top
L128 "0.5nH" LC0402N1R 6492.89,809.66 r90 top
R1 "49R9" RC0402N1R 6729.33,-174.21 r0 top
R2 "49R9" RC0402N1R 48057.92,187.58 r0 top
R3 "49R9" RC0402N1R 48228.2,187.58 r0 top
R4 "49R9" RC0402N1R 48398.48,187.58 r0 top
R5 "49R9" RC0402N1R 40146.11,187.58 r0 top
R6 "49R9" RC0402N1R 40315.41,187.58 r0 top
R7 "49R9" RC0402N1R 40485.7,187.58 r0 top
R8 "49R9" RC0402N1R 40655.98,187.58 r0 top
R9 "49R9" RC0402N1R 31937.05,187.58 r0 top
R10 "49R9" RC0402N1R 32086.66,167.89 r90 top
R11 "49R9" RC0402N1R 32326.83,187.58 r0 top
R12 "49R9" RC0402N1R 32505.98,167.89 r90 top
R13 "49R9" RC0402N1R 23537.03,167.89 r90 top
R14 "49R9" RC0402N1R 23757.52,167.89 r90 top
R15 "49R9" RC0402N1R 23977.02,167.89 r90 top
R16 "49R9" RC0402N1R 24197.5,167.89 r90 top
R17 "49R9" RC0402N1R 15068.12,167.89 r90 top
R18 "49R9" RC0402N1R 15288.6,167.89 r90 top
R19 "49R9" RC0402N1R 15508.1,167.89 r90 top
R20 "49R9" RC0402N1R 15728.58,167.89 r90 top
R21 "49R9" RC0402N1R 5742.86,167.89 r90 top
R22 "49R9" RC0402N1R 5952.51,167.89 r90 top
R23 "49R9" RC0402N1R 6182.84,167.89 r90 top
R24 "49R9" RC0402N1R 6413.17,167.89 r90 top
R25 "49R9" RC0402N1R 53989.31,482.87 r90 top
R26 "49R9" RC0402N1R 53300.3,482.87 r90 top
R27 "49R9" RC0402N1R 53529.64,482.87 r90 top
R28 "49R9" RC0402N1R 53759.97,482.87 r90 top
R29 "49R9" RC0402N1R 44550.85,482.87 r90 top
R30 "49R9" RC0402N1R 43881.53,482.87 r90 top
R31 "49R9" RC0402N1R 44110.87,482.87 r90 top
R32 "49R9" RC0402N1R 44321.51,482.87 r90 top
R33 "49R9" RC0402N1R 35112.4,482.87 r90 top
R34 "49R9" RC0402N1R 34422.41,482.87 r90 top
R35 "49R9" RC0402N1R 34652.73,482.87 r90 top
R36 "49R9" RC0402N1R 34882.08,482.87 r90 top
R37 "49R9" RC0402N1R 25623.75,482.87 r90 top
R38 "49R9" RC0402N1R 25164.08,482.87 r90 top
R39 "49R9" RC0402N1R 25393.42,482.87 r90 top
R40 "49R9" RC0402N1R 24933.76,482.87 r90 top
R41 "49R9" RC0402N1R 16098.68,482.87 r90 top
R42 "49R9" RC0402N1R 15408.68,482.87 r90 top
R43 "49R9" RC0402N1R 15638.03,482.87 r90 top
R44 "49R9" RC0402N1R 15868.35,482.87 r90 top
R45 "49R9" RC0402N1R 6432.85,482.87 r90 top
R46 "49R9" RC0402N1R 5973.18,482.87 r90 top
R47 "49R9" RC0402N1R 6202.53,482.87 r90 top
R48 "49R9" RC0402N1R 5742.86,482.87 r90 top
R49 "49R9" RC0402N1R 38671.63,809.66 r90 top
R50 "49R9" RC0402N1R 38441.3,809.66 r90 top
R51 "49R9" RC0402N1R 38231.65,809.66 r90 top
R52 "49R9" RC0402N1R 31122.05,809.66 r90 top
R53 "49R9" RC0402N1R 30891.72,809.66 r90 top
R54 "49R9" RC0402N1R 30662.38,809.66 r90 top
R55 "49R9" RC0402N1R 23642.35,809.66 r90 top
R56 "49R9" RC0402N1R 23412.03,809.66 r90 top
R57 "49R9" RC0402N1R 23182.69,809.66 r90 top
R58 "49R9" RC0402N1R 16122.3,809.66 r90 top
R59 "49R9" RC0402N1R 15892.96,809.66 r90 top
R60 "49R9" RC0402N1R 15662.63,809.66 r90 top
R61 "49R9" RC0402N1R 10923.23,809.66 r90 top
R62 "49R9" RC0402N1R 10692.9,809.66 r90 top
R63 "49R9" RC0402N1R 5973.18,809.66 r90 top
R64 "49R9" RC0402N1R 5742.86,809.66 r90 top
RF1 "AMP-PSA4-5043+" MMM1362 51028.53,138.37 r0 top
RF2 "AMP-PSA4-5043+" MMM1362 51238.19,138.37 r0 top
RF3 "AMP-PSA4-5043+" MMM1362 51468.51,138.37 r0 top
RF4 "AMP-PSA4-5043+" MMM1362 51697.86,138.37 r0 top
RF5 "AMP-PSA4-5043+" MMM1362 43555.73,138.37 r0 top
RF6 "AMP-PSA4-5043+" MMM1362 43785.07,138.37 r0 top
RF7 "AMP-PSA4-5043+" MMM1362 44015.4,138.37 r0 top
RF8 "AMP-PSA4-5043+" MMM1362 44245.72,138.37 r0 top
RF9 "AMP-PSA4-5043+" MMM1362 35496.28,138.37 r0 top
RF10 "AMP-PSA4-5043+" MMM1362 35726.6,138.37 r0 top
RF11 "AMP-PSA4-5043+" MMM1362 36006.15,138.37 r0 top
RF12 "AMP-PSA4-5043+" MMM1362 36266,138.37 r0 top
RF13 "AMP-PSA4-5043+" MMM1362 27186.82,138.37 r0 top
RF14 "AMP-PSA4-5043+" MMM1362 27467.34,138.37 r0 top
RF15 "AMP-PSA4-5043+" MMM1362 27746.88,138.37 r0 top
RF16 "AMP-PSA4-5043+" MMM1362 28027.41,138.37 r0 top
RF17 "AMP-PSA4-5043+" MMM1362 18798.61,138.37 r0 top
RF18 "AMP-PSA4-5043+" MMM1362 19078.15,138.37 r0 top
RF19 "AMP-PSA4-5043+" MMM1362 19357.7,138.37 r0 top
RF20 "AMP-PSA4-5043+" MMM1362 19638.22,138.37 r0 top
RF21 "AMP-PSA4-5043+" MMM1362 9762.74,138.37 r0 top
RF22 "AMP-PSA4-5043+" MMM1362 10032.44,138.37 r0 top
RF23 "AMP-PSA4-5043+" MMM1362 10322.81,138.37 r0 top
RF24 "AMP-PSA4-5043+" MMM1362 10612.19,138.37 r0 top
RF25 "AMP-PSA4-5043+" MMM1362 58278.89,453.34 r0 top
RF26 "AMP-PSA4-5043+" MMM1362 57699.13,453.34 r0 top
RF27 "AMP-PSA4-5043+" MMM1362 57989.5,453.34 r0 top
RF28 "AMP-PSA4-5043+" MMM1362 57409.75,453.34 r0 top
RF29 "AMP-PSA4-5043+" MMM1362 48800.08,453.34 r0 top
RF30 "AMP-PSA4-5043+" MMM1362 47950.63,453.34 r0 top
RF31 "AMP-PSA4-5043+" MMM1362 48240.99,453.34 r0 top
RF32 "AMP-PSA4-5043+" MMM1362 48510.69,453.34 r0 top
RF33 "AMP-PSA4-5043+" MMM1362 39382.29,453.34 r0 top
RF34 "AMP-PSA4-5043+" MMM1362 38512.17,453.34 r0 top
RF35 "AMP-PSA4-5043+" MMM1362 38801.56,453.34 r0 top
RF36 "AMP-PSA4-5043+" MMM1362 39091.93,453.34 r0 top
RF37 "AMP-PSA4-5043+" MMM1362 29923.17,453.34 r0 top
RF38 "AMP-PSA4-5043+" MMM1362 29343.42,453.34 r0 top
RF39 "AMP-PSA4-5043+" MMM1362 29632.8,453.34 r0 top
RF40 "AMP-PSA4-5043+" MMM1362 29053.05,453.34 r0 top
RF41 "AMP-PSA4-5043+" MMM1362 20377.43,453.34 r0 top
RF42 "AMP-PSA4-5043+" MMM1362 20088.05,453.34 r0 top
RF43 "AMP-PSA4-5043+" MMM1362 19508.29,453.34 r0 top
RF44 "AMP-PSA4-5043+" MMM1362 19797.68,453.34 r0 top
RF45 "AMP-PSA4-5043+" MMM1362 10802.16,453.34 r0 top
RF46 "AMP-PSA4-5043+" MMM1362 10222.41,453.34 r0 top
RF47 "AMP-PSA4-5043+" MMM1362 10512.78,453.34 r0 top
RF48 "AMP-PSA4-5043+" MMM1362 9932.04,453.34 r0 top
RF49 "AMP-PSA4-5043+" MMM1362 42261.37,781.11 r0 top
RF50 "AMP-PSA4-5043+" MMM1362 41741.66,781.11 r0 top
RF51 "AMP-PSA4-5043+" MMM1362 41181.6,781.11 r0 top
RF52 "AMP-PSA4-5043+" MMM1362 34822.03,781.11 r0 top
RF53 "AMP-PSA4-5043+" MMM1362 34251.14,781.11 r0 top
RF54 "AMP-PSA4-5043+" MMM1362 33671.39,781.11 r0 top
RF55 "AMP-PSA4-5043+" MMM1362 27261.62,781.11 r0 top
RF56 "AMP-PSA4-5043+" MMM1362 26722.23,781.11 r0 top
RF57 "AMP-PSA4-5043+" MMM1362 26141.49,781.11 r0 top
RF58 "AMP-PSA4-5043+" MMM1362 19792.76,781.11 r0 top
RF59 "AMP-PSA4-5043+" MMM1362 19231.71,781.11 r0 top
RF60 "AMP-PSA4-5043+" MMM1362 18651.95,781.11 r0 top
RF61 "AMP-PSA4-5043+" MMM1362 13162.51,781.11 r0 top
RF62 "AMP-PSA4-5043+" MMM1362 12872.14,781.11 r0 top
RF63 "AMP-PSA4-5043+" MMM1362 8212.47,781.11 r0 top
RF64 "AMP-PSA4-5043+" MMM1362 7923.08,781.11 r0 top

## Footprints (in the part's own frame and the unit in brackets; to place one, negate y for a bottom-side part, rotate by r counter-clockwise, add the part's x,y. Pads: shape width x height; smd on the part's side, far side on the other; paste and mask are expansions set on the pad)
CC0402N1X [mm] "Chip capacitor 0402"
  rect 0.55x0.65 smd mask+0.025: 1(-0.525,0) 2(0.525,0)
  silkscreen extent 0,-0.25 0,0.25, body extent -0.51,-0.25 0.51,0.25, height 0.5
CC0603RF1R [mil] "Chip capacitor 0603 RF pad ROUNDED PAD"
  rrect50% 25x30 smd: 1(-32,0) 2(32,0)
  silkscreen extent -8,-15 8,15, body extent -30,-15 30,15, height 28
LC0402N1R [mm] "Chip inductor 0402 ROUNDED PAD"
  rrect50% 0.6x0.65 smd: 1(-0.55,0) 2(0.55,0)
  silkscreen extent 0,-0.25 0,0.25, body extent -0.51,-0.25 0.51,0.25, height 0.5
LC1008N1R [mm] "Chip inductor 1008 ROUNDED PAD"
  rrect50% 1.25x1.45 smd: 1(-1.2,0) 2(1.2,0)
  silkscreen extent -0.3,-0.63 0.3,0.63, body extent -1.25,-1 1.25,1, height 1.35
MMM1362 [mil]
  rect 20x37 smd: 1(-25.5,-43.5) 3(25.5,43.5) 4(-25.5,43.5)
  rect 31x37 smd: 2(19.5,-43.5)
  body extent -44,-26 44,26, height 44
RC0402N1R [mm] "Chip capacitor 0402 ROUNDED PAD"
  rrect50% 0.6x0.65 smd: 1(-0.55,0) 2(0.55,0)
  silkscreen extent 0,-0.25 0,0.25, body extent -0.51,-0.25 0.51,0.25, height 0.36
